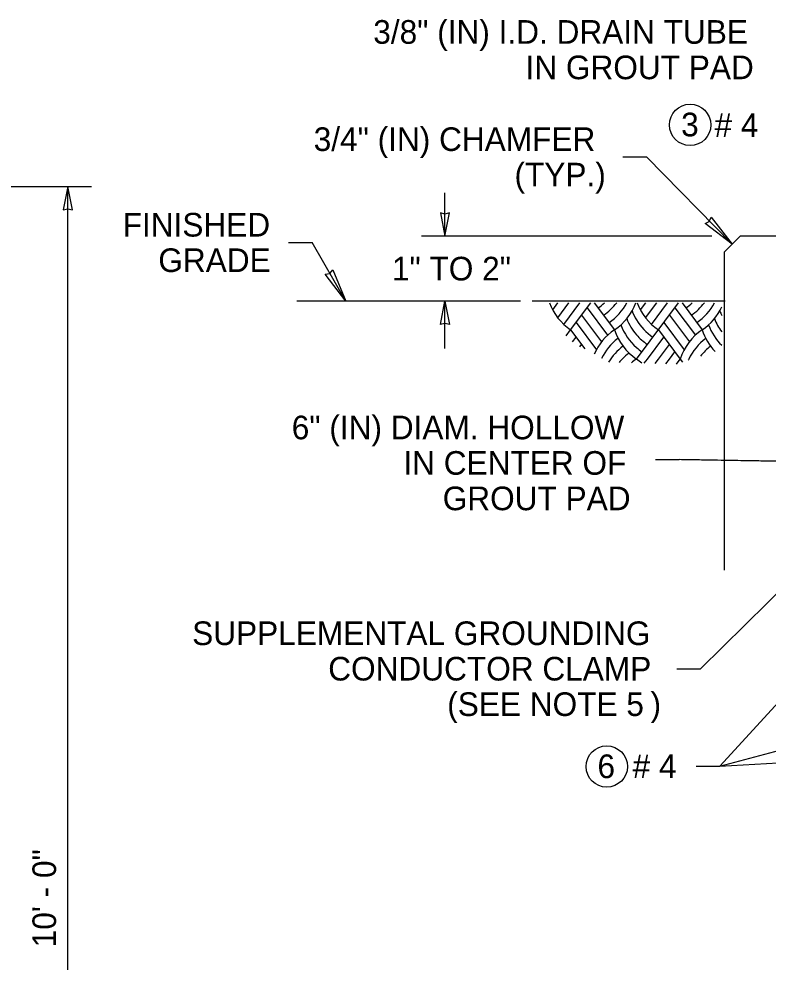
# Model space of a CAD drawing. Extents: x 99862 to 103680, y 99470 to 105076.
# Drawn here: x 101751 to 102258, y 104104 to 104743 of the extents above; entities that cross this region are included whole.
import ezdxf

# ---------------------------------------------------------------- set-up
doc = ezdxf.new("R2010")
doc.units = 0
for name, color, linetype in [('Level 1', 7, 'Continuous'), ('Level 14', 7, 'Continuous'), ('Level 15', 7, 'Continuous'), ('Level 20', 7, 'Continuous')]:
    doc.layers.add(name, color=color, linetype=linetype)

msp = doc.modelspace()

# ---------------------------------------------------------------- linework, layer by layer
at = {"layer": 'Level 1'}
for p, q in [((102239.17, 104595.51), (102228.6, 104584.95)), ((102495.29, 104595.51), (102239.17, 104595.51)), ((102228.6, 104369.45), (102228.6, 104584.95))]:
    msp.add_line(p, q, dxfattribs=at)
at = {"layer": 'Level 14'}
for p, q in [((102229.19, 104551.51), (102098.41, 104551.51)), ((102112.35, 104545.63), (102115.94, 104550.41)), ((102115.79, 104540.32), (102123.36, 104550.41)), ((102119.87, 104535.86), (102130.79, 104550.41)), ((102124.53, 104532.17), (102138.21, 104550.41)), ((102135.66, 104547.01), (102149.57, 104528.47)), ((102140.54, 104550.41), (102154.22, 104532.17)), ((102169.07, 104512.37), (102197.61, 104550.41)), ((102171.74, 104545.64), (102175.32, 104550.41)), ((102175.19, 104540.32), (102182.76, 104550.41)), ((102179.27, 104535.86), (102190.18, 104550.41)), ((102195.06, 104547.01), (102208.97, 104528.47)), ((102199.93, 104550.41), (102213.62, 104532.17)), ((102131.95, 104542.06), (102145.49, 104524.01)), ((102191.35, 104542.06), (102204.89, 104524.01)), ((102128.24, 104537.11), (102142.05, 104518.7)), ((102187.63, 104537.11), (102201.45, 104518.7)), ((102121.45, 104528.06), (102124.53, 104532.17)), ((102124.53, 104532.17), (102134.23, 104519.23)), ((102125.85, 104524.04), (102128.24, 104527.22)), ((102176.5, 104512.37), (102187.63, 104527.22)), ((102183.92, 104532.17), (102198.77, 104512.37)), ((102130.78, 104520.71), (102131.95, 104522.27)), ((102183.92, 104512.37), (102191.35, 104522.27)), ((102191.35, 104512.37), (102195.06, 104517.32)), ((102174.39, 104509.56), (102176.5, 104512.37)), ((102181.67, 104509.37), (102183.92, 104512.37)), ((102188.96, 104509.18), (102191.35, 104512.37)), ((102196.25, 104509), (102198.77, 104512.37)), ((102198.77, 104512.37), (102200.33, 104510.29))]:
    msp.add_line(p, q, dxfattribs=at)
for centre, start, end in [((102145.49, 104563.35), 200.1438, 236.09639), ((102122.13, 104578.2), 303.90361, 312.30764), ((102125.84, 104573.25), 303.90361, 322.56795), ((102129.55, 104568.3), 303.90361, 331.56909), ((102133.26, 104563.35), 303.90361, 339.8562), ((102204.88, 104563.35), 200.1438, 236.09639), ((102181.52, 104578.2), 303.90361, 312.30764), ((102185.23, 104573.25), 303.90361, 322.56795), ((102188.95, 104568.3), 303.90361, 331.56909), ((102192.66, 104563.35), 303.90361, 335.36748), ((102201.17, 104558.4), 200.87781, 211.33197), ((102260.57, 104558.4), 200.87781, 206.08639), ((102193.75, 104548.5), 200.24322, 228.95992), ((102197.46, 104553.45), 201.43438, 220.94161), ((102201.17, 104558.4), 211.33188, 236.09639), ((102253.14, 104548.5), 200.24322, 225.52885), ((102256.85, 104553.45), 201.43438, 216.93278), ((102175.18, 104500.98), 123.90361, 157.155), ((102190.03, 104543.55), 197.6434, 236.09645), ((102197.46, 104553.45), 220.94154, 236.09639), ((102234.58, 104500.98), 123.90361, 162.3566), ((102249.43, 104543.55), 197.6434, 223.8291), ((102179.15, 104496.24), 127.10056, 153.9203), ((102182.61, 104491.08), 127.10056, 149.46407), ((102238.29, 104496.03), 126.30625, 154.2266), ((102242.01, 104491.08), 127.1006, 141.86913), ((102186.32, 104486.13), 126.331, 135.71278), ((102193.75, 104548.5), 228.95986, 236.09639), ((102186.32, 104486.13), 135.71269, 140.57794), ((102190.03, 104481.18), 123.90361, 130.4399), ((102148.11, 104481.18), 49.14125, 56.09634), ((102238.29, 104496.03), 154.22654, 155.65659)]:
    msp.add_arc(centre, 37.58, start, end, dxfattribs=at)
at = {"layer": 'Level 15'}
for p, q in [((102159.77, 104649.2), (102175.77, 104649.2)), ((102233.88, 104590.23), (102175.77, 104649.2)), ((101491.07, 104629.1), (101800.13, 104629.1)), ((101784.13, 103694.63), (101784.13, 104629.1)), ((102039.44, 104595.51), (102039.44, 104624.87)), ((101933.44, 104591.28), (101949.44, 104591.28)), ((101972.4, 104551.51), (101949.44, 104591.28)), ((102220.2, 104595.51), (102023.44, 104595.51)), ((102090.55, 104551.51), (101939.21, 104551.51)), ((102039.44, 104519.51), (102039.44, 104551.51)), ((102182.05, 104444.28), (102198.05, 104444.28)), ((102283.76, 104373.01), (102212.35, 104302.77)), ((102225.48, 104236.73), (102564.13, 104327.64)), ((102290.44, 104307.74), (102225.48, 104236.73)), ((102196.35, 104302.77), (102212.35, 104302.77)), ((102225.48, 104236.73), (102419.55, 104248.48)), ((102209.48, 104236.73), (102225.48, 104236.73))]:
    msp.add_line(p, q, dxfattribs=at)
for points in [[(101784.13, 104629.1), (101781.05, 104613.38), (101784.13, 104614.1), (101787.22, 104613.38)], [(102039.44, 104595.51), (102042.53, 104611.23), (102039.44, 104610.51), (102036.36, 104611.23)], [(102233.88, 104590.23), (102215.5, 104604.09), (102218.35, 104605.48), (102219.68, 104608.35)], [(101972.4, 104551.51), (101958.4, 104569.79), (101961.51, 104570.36), (101963.57, 104572.77)], [(102039.44, 104551.51), (102042.53, 104535.78), (102039.44, 104536.51), (102036.36, 104535.78)]]:
    msp.add_lwpolyline(points, close=True, dxfattribs=at)
msp.add_open_spline([(102443.58, 104595.51), (102421.98, 104550.72), (102393.6, 104508.61), (102352.02, 104466.95), (102318.21, 104448.55), (102274.63, 104442.92), (102250.28, 104443.42), (102198.05, 104444.28)], degree=2, dxfattribs=at)
at = {"layer": 'Level 20'}
for centre in [(102205.41, 104670.86), (102148.97, 104236.56)]:
    msp.add_circle(centre, 14, dxfattribs=at)

# ---------------------------------------------------------------- texts
for s, p in [('3/8" (IN) I.D. DRAIN TUBE', (101990.89, 104725.79)), ('IN GROUT PAD', (102093.97, 104701.79)), ('3', (102199.32, 104663.13)), ('    # 4', (102198.12, 104662.77)), ('3/4" (IN) CHAMFER', (101950.57, 104653.2)), ('(TYP.)', (102086.5, 104629.2)), ('FINISHED', (101821.22, 104595.28)), ('GRADE', (101845.37, 104571.28)), ('1" TO 2"', (102003.52, 104565.58)), ('6" (IN) DIAM. HOLLOW', (101935.7, 104458.05)), (' IN CENTER OF ', (102005.32, 104434.05)), ('GROUT PAD', (102037.9, 104410.05)), ('SUPPLEMENTAL GROUNDING', (101868.28, 104318.77)), ('CONDUCTOR CLAMP', (101960.39, 104294.77)), ('(SEE NOTE 5', (102040.96, 104270.77)), (')', (102178.61, 104270.77)), ('6  # 4', (102142.67, 104228.73))]:
    msp.add_text(s, height=16, dxfattribs=at).set_placement(p)
msp.add_text('10\' - 0"', height=16, rotation=90, dxfattribs=at).set_placement((101776.13, 104114.18))

doc.saveas('drawing.dxf')
